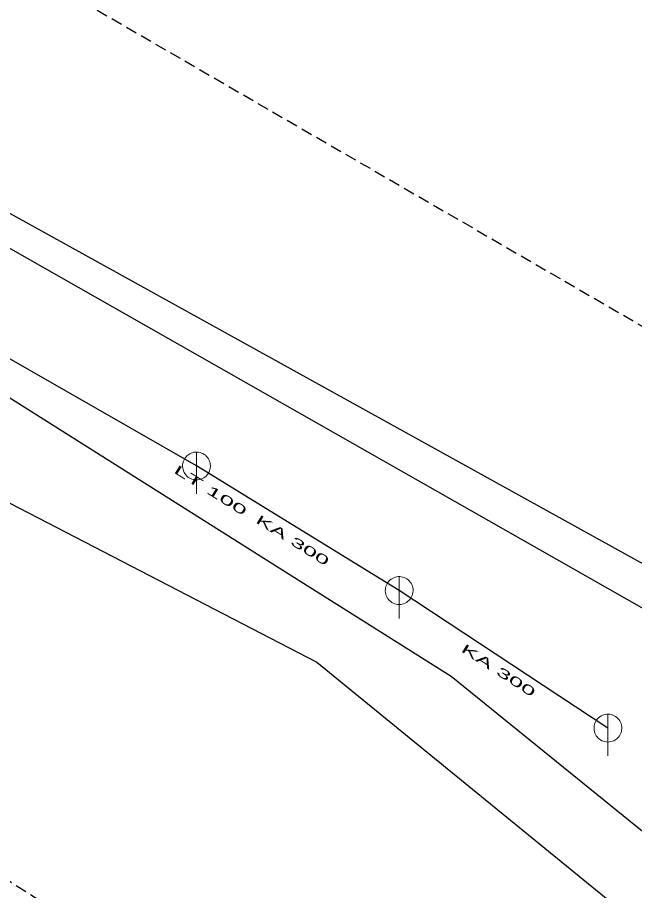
# Model space of a CAD drawing. Extents: x -687593 to -687108, y -975254 to -974717.
# Drawn here: x -687352.8 to -687308.5, y -974990.1 to -974927.4 of the extents above; entities that cross this region are included whole.
import ezdxf
from ezdxf.enums import TextEntityAlignment as Align

# ---------------------------------------------------------------- set-up
doc = ezdxf.new("R2010")
doc.units = 0
doc.header["$LTSCALE"] = 0.27
doc.linetypes.add('MEDIUM_DASHED', pattern=[4.5, 3, -1.5])
for name, color, linetype, lineweight in [('1', 7, 'Continuous', 25), ('14', 7, 'Continuous', 13), ('17', 7, 'Continuous', 25), ('22', 7, 'Continuous', 13), ('63', 7, 'MEDIUM_DASHED', 25)]:
    doc.layers.add(name, color=color, linetype=linetype, lineweight=lineweight)

msp = doc.modelspace()

# ---------------------------------------------------------------- linework, layer by layer
at = {"layer": '1'}
msp.add_lwpolyline([(-687190.553, -975166.941), (-687164.86, -975177.861), (-687155.924, -975158.837), (-687125.348, -975155.541), (-687124.826, -975139.621), (-687173.065, -975131.89), (-687231.828, -975028.025), (-687222.959, -975015.464), (-687237.898, -975004.026), (-687247.4, -975009.654), (-687276.892, -974983.781), (-687453.606, -974886.044), (-687460.232, -974860.45), (-687474.874, -974858.564), (-687482.889, -974882.272), (-687502.421, -974882.802), (-687499.452, -974907.164), (-687464.42, -974904.824), (-687331.319, -974973.728), (-687252.566, -975037.916), (-687192.379, -975151.48)], close=True, dxfattribs=at)
at = {"layer": '14', "lineweight": 25}
for p, q in [((-687339.967, -974959.63), (-687373.818, -974940.214)), ((-687325.387, -974968.58), (-687339.967, -974959.63)), ((-687310.374, -974978.468), (-687325.387, -974968.58))]:
    msp.add_line(p, q, dxfattribs=at)
at = {"layer": '17'}
for points in [[(-687435.81, -974897.134), (-687294.34, -974977.541), (-687214.33, -974877.654)], [(-687358.699, -974951.407), (-687333.097, -974967.52), (-687321.645, -974974.737), (-687306.885, -974986.7), (-687303.706, -974988.972)]]:
    msp.add_lwpolyline(points, dxfattribs=at)
at = {"layer": '22'}
for p, q in [((-687339.967, -974961.63), (-687339.966, -974958.63)), ((-687325.387, -974970.58), (-687325.386, -974967.58)), ((-687310.374, -974980.468), (-687310.373, -974977.468))]:
    msp.add_line(p, q, dxfattribs=at)
for points in [[(-687338.967, -974959.63), (-687338.972, -974959.521), (-687338.99, -974959.413), (-687339.02, -974959.307), (-687339.06, -974959.206), (-687339.112, -974959.109), (-687339.174, -974959.019), (-687339.246, -974958.936), (-687339.326, -974958.862), (-687339.414, -974958.796), (-687339.508, -974958.741), (-687339.608, -974958.696), (-687339.713, -974958.663), (-687339.82, -974958.641), (-687339.929, -974958.631), (-687340.039, -974958.633), (-687340.147, -974958.647), (-687340.254, -974958.672), (-687340.357, -974958.709), (-687340.455, -974958.758), (-687340.547, -974958.816), (-687340.633, -974958.885), (-687340.71, -974958.962), (-687340.779, -974959.048), (-687340.838, -974959.14), (-687340.886, -974959.238), (-687340.923, -974959.341), (-687340.949, -974959.448), (-687340.963, -974959.556), (-687340.966, -974959.666), (-687340.956, -974959.775), (-687340.935, -974959.882), (-687340.901, -974959.986), (-687340.857, -974960.086), (-687340.802, -974960.181), (-687340.736, -974960.269), (-687340.662, -974960.349), (-687340.579, -974960.421), (-687340.489, -974960.483), (-687340.393, -974960.535), (-687340.291, -974960.576), (-687340.186, -974960.606), (-687340.078, -974960.624), (-687339.968, -974960.63), (-687339.859, -974960.624), (-687339.751, -974960.606), (-687339.646, -974960.577), (-687339.544, -974960.536), (-687339.447, -974960.484), (-687339.357, -974960.422), (-687339.274, -974960.351), (-687339.199, -974960.271), (-687339.134, -974960.183), (-687339.078, -974960.089), (-687339.034, -974959.989), (-687339, -974959.885), (-687338.978, -974959.777), (-687338.968, -974959.668)], [(-687324.387, -974968.58), (-687324.392, -974968.471), (-687324.41, -974968.363), (-687324.44, -974968.257), (-687324.48, -974968.156), (-687324.532, -974968.059), (-687324.594, -974967.969), (-687324.666, -974967.886), (-687324.746, -974967.812), (-687324.834, -974967.746), (-687324.928, -974967.691), (-687325.028, -974967.646), (-687325.133, -974967.613), (-687325.24, -974967.591), (-687325.349, -974967.581), (-687325.459, -974967.583), (-687325.567, -974967.597), (-687325.674, -974967.622), (-687325.777, -974967.659), (-687325.875, -974967.708), (-687325.967, -974967.766), (-687326.053, -974967.835), (-687326.13, -974967.912), (-687326.199, -974967.998), (-687326.258, -974968.09), (-687326.306, -974968.188), (-687326.343, -974968.291), (-687326.369, -974968.398), (-687326.383, -974968.506), (-687326.386, -974968.616), (-687326.376, -974968.725), (-687326.355, -974968.832), (-687326.321, -974968.936), (-687326.277, -974969.036), (-687326.222, -974969.131), (-687326.156, -974969.219), (-687326.082, -974969.299), (-687325.999, -974969.371), (-687325.909, -974969.433), (-687325.813, -974969.485), (-687325.711, -974969.526), (-687325.606, -974969.556), (-687325.498, -974969.574), (-687325.388, -974969.58), (-687325.279, -974969.574), (-687325.171, -974969.556), (-687325.066, -974969.527), (-687324.964, -974969.486), (-687324.867, -974969.434), (-687324.777, -974969.372), (-687324.694, -974969.301), (-687324.619, -974969.221), (-687324.554, -974969.133), (-687324.498, -974969.039), (-687324.454, -974968.939), (-687324.42, -974968.835), (-687324.398, -974968.727), (-687324.388, -974968.618)], [(-687309.374, -974978.468), (-687309.379, -974978.359), (-687309.397, -974978.251), (-687309.427, -974978.145), (-687309.467, -974978.044), (-687309.519, -974977.947), (-687309.581, -974977.857), (-687309.653, -974977.774), (-687309.733, -974977.7), (-687309.821, -974977.634), (-687309.915, -974977.579), (-687310.015, -974977.534), (-687310.12, -974977.501), (-687310.227, -974977.479), (-687310.336, -974977.469), (-687310.446, -974977.471), (-687310.554, -974977.485), (-687310.661, -974977.51), (-687310.764, -974977.547), (-687310.862, -974977.596), (-687310.954, -974977.654), (-687311.04, -974977.723), (-687311.117, -974977.8), (-687311.186, -974977.886), (-687311.245, -974977.978), (-687311.293, -974978.076), (-687311.33, -974978.179), (-687311.356, -974978.286), (-687311.37, -974978.394), (-687311.373, -974978.504), (-687311.363, -974978.613), (-687311.342, -974978.72), (-687311.308, -974978.824), (-687311.264, -974978.924), (-687311.209, -974979.019), (-687311.143, -974979.107), (-687311.069, -974979.187), (-687310.986, -974979.259), (-687310.896, -974979.321), (-687310.8, -974979.373), (-687310.698, -974979.414), (-687310.593, -974979.444), (-687310.485, -974979.462), (-687310.375, -974979.468), (-687310.266, -974979.462), (-687310.158, -974979.444), (-687310.053, -974979.415), (-687309.951, -974979.374), (-687309.854, -974979.322), (-687309.764, -974979.26), (-687309.681, -974979.189), (-687309.606, -974979.109), (-687309.541, -974979.021), (-687309.485, -974978.927), (-687309.441, -974978.827), (-687309.407, -974978.723), (-687309.385, -974978.615), (-687309.375, -974978.506)]]:
    msp.add_lwpolyline(points, close=True, dxfattribs=at)
at = {"layer": '63'}
msp.add_lwpolyline([(-687526.998, -974914.677), (-687484.572, -974843.781), (-687484.572, -974843.781), (-687425.956, -974881.183), (-687425.956, -974881.183), (-687214.941, -975003.438), (-687214.941, -975003.438), (-687108.316, -975140.766), (-687108.316, -975140.766), (-687138.461, -975189.333), (-687138.461, -975189.333), (-687208.242, -975184.867), (-687208.242, -975184.867), (-687273.556, -975040.84), (-687273.556, -975040.84), (-687454.985, -974924.168), (-687454.985, -974924.168)], close=True, dxfattribs=at)

# ---------------------------------------------------------------- texts
at = {"layer": '1'}
for s, rotation, width, p in [('LT 100', 328, 2.15, (-687339.1326, -974961.653)), ('LT 100', 328, 2.15, (-687339.1326, -974961.653)), ('LT 100', 328, 2.15, (-687339.1326, -974961.653)), ('LT 100', 328, 2.15, (-687339.1326, -974961.653)), ('LT 100', 328, 2.15, (-687339.1326, -974961.653)), ('KA 300', 328, 2.05, (-687333.2246, -974965.253)), ('KA 300', 328, 2.05, (-687333.2246, -974965.253)), ('KA 300', 328, 2.05, (-687333.2246, -974965.253)), ('KA 300', 328, 2.05, (-687333.2246, -974965.253)), ('KA 300', 328, 2.05, (-687333.2246, -974965.253)), ('KA 300', 327, 2.1, (-687318.4265, -974974.5968)), ('KA 300', 327, 2.1, (-687318.4265, -974974.5968)), ('KA 300', 327, 2.1, (-687318.4265, -974974.5968)), ('KA 300', 327, 2.1, (-687318.4265, -974974.5968)), ('KA 300', 327, 2.1, (-687318.4265, -974974.5968))]:
    msp.add_text(s, height=0.6667, rotation=rotation, dxfattribs=dict(at, width=width)).set_placement(p, align=Align.CENTER)

doc.saveas('drawing.dxf')
